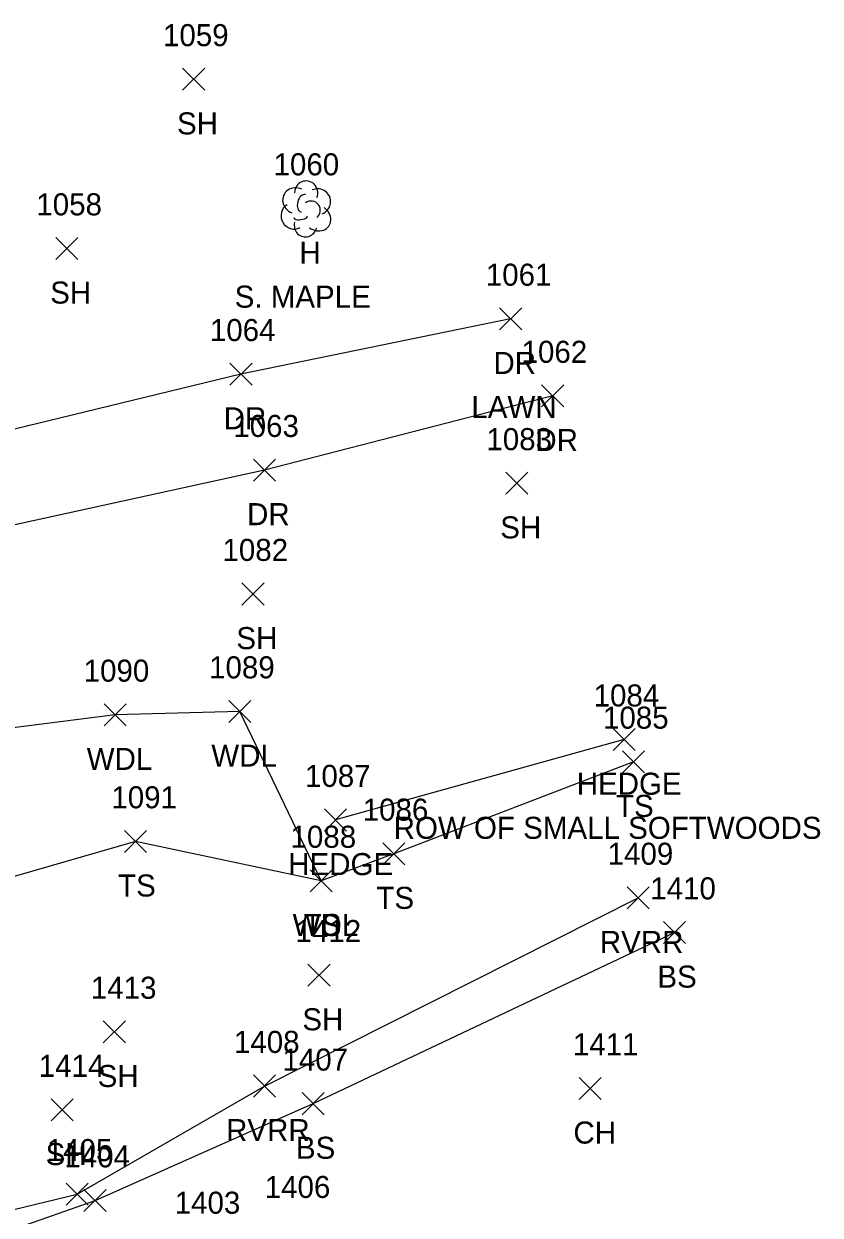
# Model space of a CAD drawing. Extents: x 1678553 to 1680768, y 787260 to 792325.
# Drawn here: x 1678762.7 to 1678834.9, y 787588.2 to 787696.3 of the extents above; entities that cross this region are included whole.
import ezdxf

# ---------------------------------------------------------------- set-up
doc = ezdxf.new("R2010")
doc.units = 0
for name, color, linetype in [('L_A', 7, 'Continuous'), ('L_C', 7, 'Continuous'), ('L_I', 7, 'Continuous'), ('L_TIC', 7, 'Continuous'), ('LAHR', 7, 'Continuous'), ('LAWA', 7, 'Continuous'), ('LAWE', 7, 'Continuous'), ('LELB', 7, 'Continuous'), ('LTD', 7, 'Continuous'), ('R_A', 7, 'Continuous'), ('R_C', 7, 'Continuous'), ('R_I', 7, 'Continuous'), ('R_TIC', 7, 'Continuous'), ('RDP', 7, 'Continuous')]:
    doc.layers.add(name, color=color, linetype=linetype)

msp = doc.modelspace()

# ---------------------------------------------------------------- linework, layer by layer
at = {"layer": 'L_TIC'}
for points in [[(1678777.1, 787690.23), (1678779.1, 787692.23)], [(1678779.1, 787690.23), (1678777.1, 787692.23)], [(1678765.61, 787674.89), (1678767.61, 787676.89)], [(1678767.61, 787674.89), (1678765.61, 787676.89)], [(1678806.4, 787653.6), (1678808.4, 787655.6)], [(1678808.4, 787653.6), (1678806.4, 787655.6)], [(1678782.48, 787643.56), (1678784.48, 787645.56)], [(1678784.48, 787643.56), (1678782.48, 787645.56)], [(1678769.99, 787632.61), (1678771.99, 787634.61)], [(1678771.99, 787632.61), (1678769.99, 787634.61)], [(1678781.28, 787632.91), (1678783.28, 787634.91)], [(1678783.28, 787632.91), (1678781.28, 787634.91)], [(1678816.12, 787630.36), (1678818.12, 787632.36)], [(1678818.12, 787630.36), (1678816.12, 787632.36)], [(1678816.97, 787628.35), (1678818.97, 787630.35)], [(1678818.97, 787628.35), (1678816.97, 787630.35)], [(1678789.96, 787623.07), (1678791.96, 787625.07)], [(1678791.96, 787623.07), (1678789.96, 787625.07)], [(1678771.84, 787621.13), (1678773.84, 787623.13)], [(1678773.84, 787621.13), (1678771.84, 787623.13)], [(1678795.25, 787620.01), (1678797.25, 787622.01)], [(1678797.25, 787620.01), (1678795.25, 787622.01)], [(1678788.66, 787617.55), (1678790.66, 787619.55)], [(1678790.66, 787617.55), (1678788.66, 787619.55)], [(1678788.66, 787617.55), (1678790.66, 787619.55)], [(1678790.66, 787617.55), (1678788.66, 787619.55)], [(1678817.4, 787616.01), (1678819.4, 787618.01)], [(1678819.4, 787616.01), (1678817.4, 787618.01)], [(1678820.69, 787612.87), (1678822.69, 787614.87)], [(1678822.69, 787612.87), (1678820.69, 787614.87)], [(1678788.46, 787609), (1678790.46, 787611)], [(1678790.46, 787609), (1678788.46, 787611)], [(1678769.91, 787603.86), (1678771.91, 787605.86)], [(1678771.91, 787603.86), (1678769.91, 787605.86)], [(1678783.53, 787598.95), (1678785.53, 787600.95)], [(1678785.53, 787598.95), (1678783.53, 787600.95)], [(1678813.03, 787598.73), (1678815.03, 787600.73)], [(1678815.03, 787598.73), (1678813.03, 787600.73)], [(1678787.93, 787597.35), (1678789.93, 787599.35)], [(1678789.93, 787597.35), (1678787.93, 787599.35)], [(1678765.19, 787596.78), (1678767.19, 787598.78)], [(1678767.19, 787596.78), (1678765.19, 787598.78)], [(1678766.55, 787589.14), (1678768.55, 787591.14)], [(1678768.55, 787589.14), (1678766.55, 787591.14)], [(1678768.16, 787588.57), (1678770.16, 787590.57)], [(1678770.16, 787588.57), (1678768.16, 787590.57)]]:
    msp.add_lwpolyline(points, dxfattribs=at)
at = {"layer": 'LAHR'}
msp.add_lwpolyline([(1678817.12, 787631.36), (1678790.96, 787624.07)], dxfattribs=at)
at = {"layer": 'LAWA'}
msp.add_lwpolyline([(1678789.66, 787618.55), (1678782.28, 787633.91), (1678770.99, 787633.61), (1678749.84, 787630.92), (1678727.88, 787628.09), (1678728.53, 787616.43), (1678733.15, 787607.22), (1678734.09, 787597.69), (1678727.59, 787595.66), (1678724.83, 787595.57), (1678720.12, 787590.44), (1678719.43, 787582.2)], dxfattribs=at)
at = {"layer": 'LAWE'}
msp.add_lwpolyline([(1678722.67, 787582.69), (1678729.64, 787581.87), (1678749.3, 787585.72), (1678767.55, 787590.14), (1678784.53, 787599.95), (1678818.4, 787617.01)], dxfattribs=at)
at = {"layer": 'LELB'}
for points in [[(1678817.97, 787629.35), (1678796.25, 787621.01), (1678789.66, 787618.55), (1678772.84, 787622.13), (1678755.53, 787617.14), (1678737.34, 787609.22), (1678733.15, 787607.22)], [(1678720.9, 787579.97), (1678730.54, 787579.83), (1678747.48, 787581.94), (1678769.16, 787589.57), (1678788.93, 787598.35), (1678821.69, 787613.87)]]:
    msp.add_lwpolyline(points, dxfattribs=at)
at = {"layer": 'LTD'}
msp.add_line((1678788.25, 787679.52), (1678788.25, 787679.52), dxfattribs=at)
msp.add_line((1678788.25, 787679.52), (1678788.25, 787679.52), dxfattribs=at)
msp.add_arc((1678788.3, 787680.96), 1.05, 335.5272, 180.9563, dxfattribs=at)
for centre, major_axis, ratio, start_param, end_param in [((1678787.46, 787680.19), (1.21, -0.51), 0.895232, 1.570796, 4.712389), ((1678789.29, 787680.11), (-1.14, -0.48), 0.949671, 1.570796, 4.712389), ((1678788.04, 787679.98), (-0.208, -0.792), 0.645439, 3.141593, 6.283185), ((1678787.17, 787678.82), (0.58, -1.04), 0.959034, 3.141593, 6.283185), ((1678788.75, 787679.36), (-0.5, 0.667), 0.989748, 3.141593, 6.283185), ((1678789.25, 787678.69), (-1.09, 0.79), 0.841452, 1.570796, 4.712389), ((1678788.25, 787678.02), (0.26, 1.06), 0.942809, 1.570796, 4.712389), ((1678787.79, 787678.77), (-0.625, -0.083), 0.423636, 0, 3.141593)]:
    msp.add_ellipse(centre, major_axis=major_axis, ratio=ratio, start_param=start_param, end_param=end_param, dxfattribs=at)
at = {"layer": 'R_TIC'}
for points in [[(1678805.83, 787668.51), (1678807.83, 787670.51)], [(1678807.83, 787668.51), (1678805.83, 787670.51)], [(1678781.39, 787663.49), (1678783.39, 787665.49)], [(1678783.39, 787663.49), (1678781.39, 787665.49)], [(1678809.64, 787661.52), (1678811.64, 787663.52)], [(1678811.64, 787661.52), (1678809.64, 787663.52)], [(1678783.51, 787654.8), (1678785.51, 787656.8)], [(1678785.51, 787654.8), (1678783.51, 787656.8)]]:
    msp.add_lwpolyline(points, dxfattribs=at)
at = {"layer": 'RDP'}
for points in [[(1678806.83, 787669.51), (1678782.39, 787664.49), (1678750.91, 787656.85), (1678730, 787652.74), (1678725.3, 787652.23), (1678717.39, 787651.57), (1678712.68, 787651.27)], [(1678810.64, 787662.52), (1678784.51, 787655.8), (1678750.83, 787648.41), (1678734.05, 787644.53)]]:
    msp.add_lwpolyline(points, dxfattribs=at)

# ---------------------------------------------------------------- texts
at = {"layer": 'L_A'}
for s, p in [('SH', (1678776.59, 787686.23)), ('H', (1678787.68, 787674.52)), ('SH', (1678765.1, 787670.89)), ('SH', (1678805.89, 787649.6)), ('SH', (1678781.97, 787639.56)), ('WDL', (1678779.7, 787628.91)), ('WDL', (1678768.41, 787628.61)), ('HEDGE', (1678812.82, 787626.36)), ('TS', (1678816.38, 787624.35)), ('HEDGE', (1678786.67, 787619.07)), ('TS', (1678771.25, 787617.13)), ('TS', (1678794.66, 787616.01)), ('WDL', (1678787.07, 787613.55)), ('TS', (1678788.07, 787613.55)), ('RVRR', (1678814.91, 787612.01)), ('BS', (1678820.13, 787608.87)), ('SH', (1678787.95, 787605)), ('SH', (1678769.4, 787599.86)), ('RVRR', (1678781.04, 787594.95)), ('CH', (1678812.52, 787594.73)), ('BS', (1678787.37, 787593.35)), ('SH', (1678764.68, 787592.78))]:
    msp.add_text(s, height=2, dxfattribs=at).set_placement(p)
at = {"layer": 'L_C'}
for s, p in [('S. MAPLE', (1678781.82, 787670.52)), ('ROW OF SMALL SOFTWOODS', (1678796.23, 787622.36))]:
    msp.add_text(s, height=2, dxfattribs=at).set_placement(p)
at = {"layer": 'L_I'}
for s, p in [('1059', (1678775.32, 787694.23)), ('1060', (1678785.34, 787682.52)), ('1058', (1678763.84, 787678.89)), ('1083', (1678804.63, 787657.6)), ('1082', (1678780.71, 787647.56)), ('1090', (1678768.13, 787636.61)), ('1089', (1678779.5, 787636.91)), ('1084', (1678814.35, 787634.36)), ('1085', (1678815.2, 787632.35)), ('1087', (1678788.19, 787627.07)), ('1091', (1678770.64, 787625.13)), ('1086', (1678793.42, 787624.01)), ('1088', (1678786.88, 787621.55)), ('1088', (1678786.88, 787621.55)), ('1409', (1678815.62, 787620.01)), ('1410', (1678819.48, 787616.87)), ('1412', (1678787.33, 787613)), ('1413', (1678768.78, 787607.86)), ('1408', (1678781.75, 787602.95)), ('1411', (1678812.47, 787602.73)), ('1414', (1678764.06, 787600.78)), ('1407', (1678786.15, 787601.35)), ('1405', (1678764.78, 787593.14)), ('1404', (1678766.38, 787592.57)), ('1406', (1678784.54, 787589.8)), ('1403', (1678776.38, 787588.37))]:
    msp.add_text(s, height=2, dxfattribs=at).set_placement(p)
at = {"layer": 'R_A'}
for p in [(1678805.27, 787664.51), (1678780.82, 787659.49), (1678809.07, 787657.52), (1678782.94, 787650.8)]:
    msp.add_text('DR', height=2, dxfattribs=at).set_placement(p)
at = {"layer": 'R_C'}
msp.add_text('LAWN', height=2, dxfattribs=at).set_placement((1678803.27, 787660.51))
at = {"layer": 'R_I'}
for s, p in [('1061', (1678804.58, 787672.51)), ('1064', (1678779.57, 787667.49)), ('1062', (1678807.82, 787665.52)), ('1063', (1678781.69, 787658.8))]:
    msp.add_text(s, height=2, dxfattribs=at).set_placement(p)

doc.saveas('drawing.dxf')
